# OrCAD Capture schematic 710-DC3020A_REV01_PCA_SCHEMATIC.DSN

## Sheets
1 LT8637: size Custom; company: ANALOG DEVICES; note: SILENT SWITCHER WITH 2.5uA QUIESCENT CURRENT; note: 42V, 5A(7A PEAK) SYNCHRONOUS STEP-DOWN
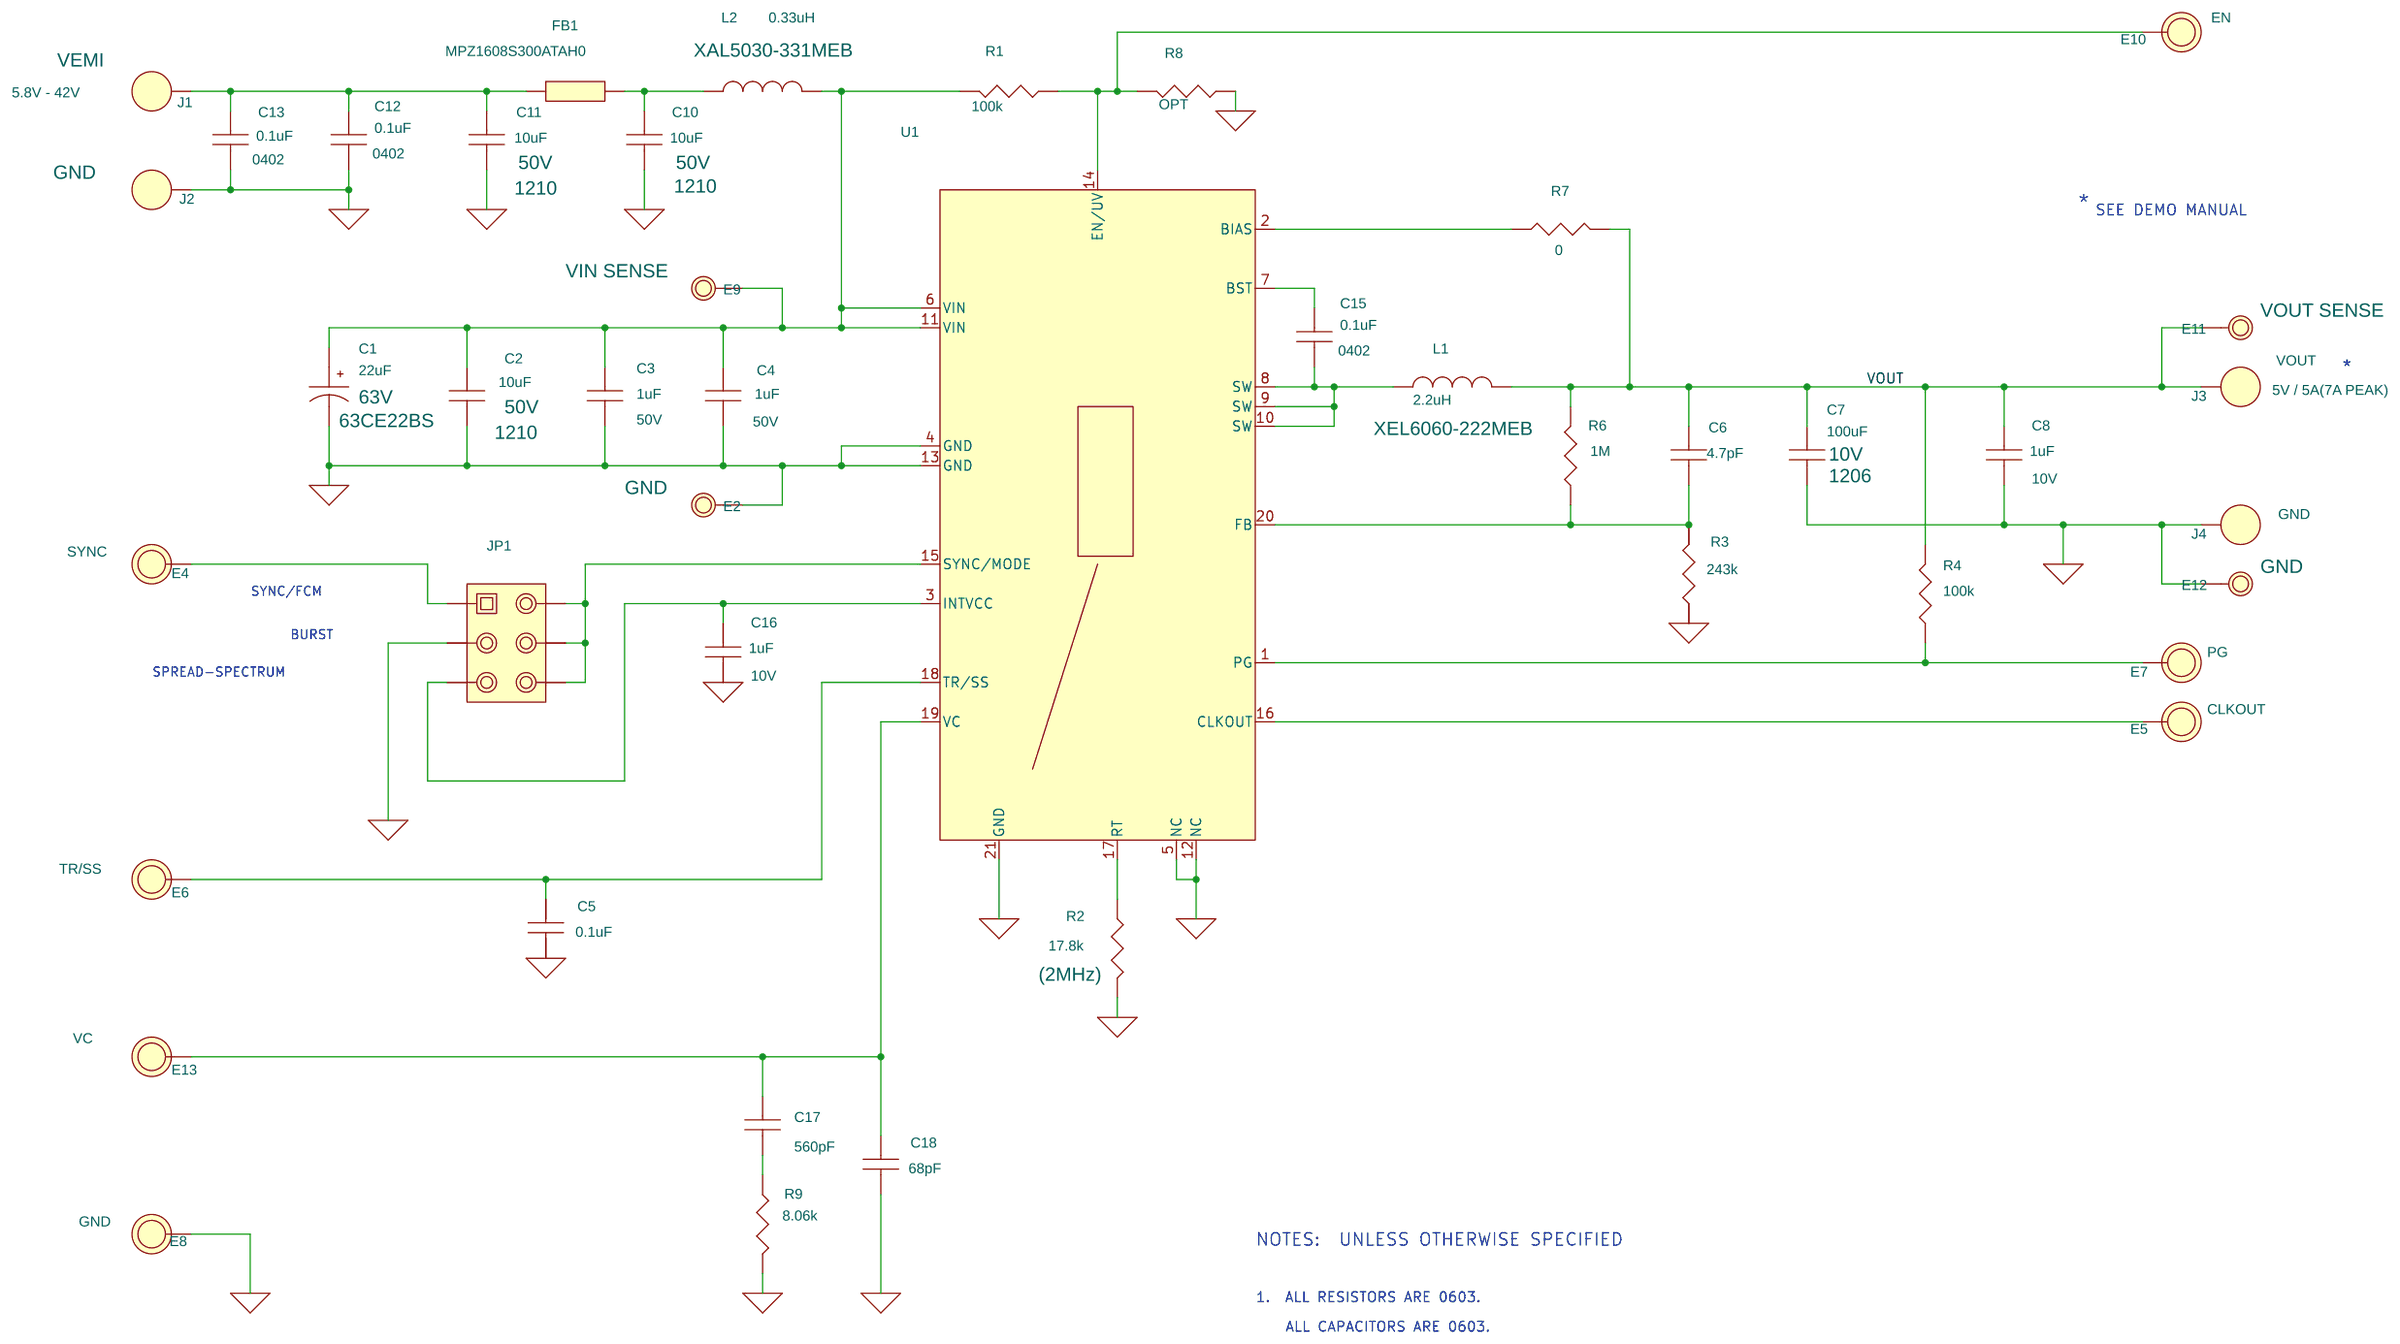
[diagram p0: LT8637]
2 PAGE2
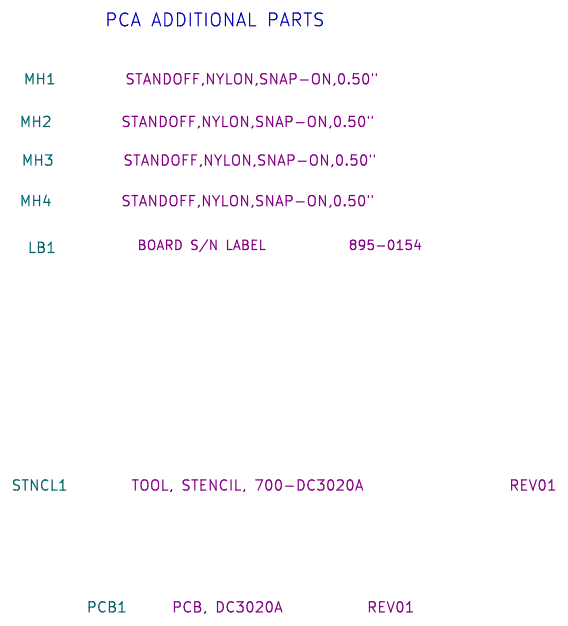
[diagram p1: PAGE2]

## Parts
sheet LT8637
C1  22uF  [SUNCON_CE-BS_6.3X7.7]
C2  10uF  [CC1210N]
C3  1uF  [CC0603N]
C4  1uF  [CC0603N]
C5  0.1uF  [CC0603N]
C6  4.7pF  [CC0603N]
C7  100uF  [CC1206N]
C8  1uF  [CC0603N]
C10  10uF  [CC1210N]
C11  10uF  [CC1210N]
C12  0.1uF  [CC0402N]
C13  0.1uF  [CC0402N]
C15  0.1uF  [CC0402N]
C16  1uF  [CC0603N]
C17  560pF  [CC0603N]
C18  68pF  [CC0603N]
E2  TEST POINT  [MILLMAX2308]
E4  TEST POINT  [MILLMAX2501]
E5  TEST POINT  [MILLMAX2501]
E6  TEST POINT  [MILLMAX2501]
E7  TEST POINT  [MILLMAX2501]
E8  TEST POINT  [MILLMAX2501]
E9  TEST POINT  [MILLMAX2308]
E10  TEST POINT  [MILLMAX2501]
E11  TEST POINT  [MILLMAX2308]
E12  TEST POINT  [MILLMAX2308]
E13  TEST POINT  [MILLMAX2501]
FB1  30 OHMS@100Mhz  [IND0603N]
J1  BANANA JACK  [KEY-575-4]
J2  BANANA JACK  [KEY-575-4]
J3  BANANA JACK  [KEY-575-4]
J4  BANANA JACK  [KEY-575-4]
JP1  HDR  [HD2X3-079]
L1  2.2uH  [COILCRAFT-XEL6060]
L2  0.33uH  [COILCRAFT-XAL50]
R1  100k  [CR0603N]
R2  17.8k  [CR0603N]
R3  243k  [CR0603N]
R4  100k  [CR0603N]
R6  1M  [CR0603N]
R7  0  [CR0603N]
R8  OPT  [CR0603N]
R9  8.06k  [CR0603N]
U1  LT8637-EV  [LTC-LQFN-20-1602]
XJP1  SHUNT  [SAMTEC-SHUNT-079]
sheet PAGE2
LB1  LABEL  [895-0154_REV01]
MH1  STANDOFF  [KEYSTONE_8829-8834]
MH2  STANDOFF  [KEYSTONE_8829-8834]
MH3  STANDOFF  [KEYSTONE_8829-8834]
MH4  STANDOFF  [KEYSTONE_8829-8834]
PCB1  PCB, DC3020A
STNCL1  TOOL, STENCIL, 700-DC3020A

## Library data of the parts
C1 = CAP_P_ALT: CAP.,22uF,ALUM ELECT,63V,20%,6.3x7.7mm,CE-BS Series; CLASS: DISCRETE; Dielectric Type: ALUM ELECT; Inventory Qty: 35661; Manufacturer: SUN ELECTRONIC INDUSTRIES CORP; Manufacturer PN: 63CE22BS; PART_NUMBER: 150-3334; Package Size: 6.3x7.7mm; Rated Voltage: 63V; Tolerance: 20%
C2 C10 C11 = CAP: CAP.,10uF,X7R,50V,10%,1210,NO SUBS. ALLOWED; CLASS: DISCRETE; Dielectric Type: X7R; FPLIST: CC1210N,CC1210L,CC1210M; Inventory Qty: 191942; Manufacturer: MURATA; Manufacturer PN: GRM32ER71H106KA12L; PART_NUMBER: 150-3043; Package Size: 1210; Package Type: SMD; Rated Voltage: 50V; Tolerance: 10%
C3 C4 = CAP: CAP.,1uF,X5R,50V,10%,0603; CLASS: DISCRETE; Dielectric Type: X5R; FPLIST: CC0603N,CC0603L,CC0603M; Inventory Qty: 11270; Manufacturer: AVX; Manufacturer PN: 06035D105KAT2A; PART_NUMBER: 150-3292; Package Size: 0603; Package Type: SMD; Rated Voltage: 50V; Tolerance: 10%
C5 = CAP: CAP.,0.1uF,X7R,16V,10%,0603; CLASS: DISCRETE; Dielectric Type: X7R; FPLIST: CC0603N,CC0603L,CC0603M; Inventory Qty: 38869; Manufacturer: MURATA; Manufacturer PN: GRM188R71C104KA01D; PART_NUMBER: 150-0018; Package Size: 0603; Package Type: SMD; Rated Voltage: 16V; Tolerance: 10%
C6 = CAP: CAP.,4.7pF,C0G/NP0,50V,+/-0.25pF,0603; CLASS: DISCRETE; Dielectric Type: C0G/NP0; FPLIST: CC0603N,CC0603L,CC0603M; Inventory Qty: 22709; Manufacturer: MURATA; Manufacturer PN: GRM1885C1H4R7CA01D; PART_NUMBER: 150-2223; Package Size: 0603; Rated Voltage: 50V; Tolerance: +/-0.25pF
C7 = CAP: CAP.,100uF,X5R,10V,20%,1206; CLASS: DISCRETE; Dielectric Type: X5R; FPLIST: CC1206N,CC1206L,CC1206M; Inventory Qty: 10889; Manufacturer: TDK; Manufacturer PN: C3216X5R1A107M160AC; PART_NUMBER: 150-2343; Package Size: 1206; Package Type: SMD; Rated Voltage: 10V; Tolerance: 20%
C8 C16 = CAP: CAP.,1uF,X7R,10V,10%,0603; CLASS: DISCRETE; Dielectric Type: X7R; FPLIST: CC0603N,CC0603L,CC0603M; Inventory Qty: 56548; Manufacturer: AVX; Manufacturer PN: 0603ZC105KAT2A; PART_NUMBER: 150-3414; Package Size: 0603; Rated Voltage: 10V; Tolerance: 10%
C12 C13 C15 = CAP: CAP.,0.1uF,X7R,50V,10%,0402; CLASS: DISCRETE; Dielectric Type: X7R; FPLIST: CC0402N,CC0402L,CC0402M; Inventory Qty: 321916; Manufacturer: AVX; Manufacturer PN: 04025C104KAT2A; PART_NUMBER: 150-3240; Package Size: 0402; Package Type: SMD; Rated Voltage: 50V; Tolerance: 10%
C17 = CAP: CAP.,560pF,C0G,50V,5%,0603; CLASS: DISCRETE; Dielectric Type: C0G; FPLIST: CC0603N,CC0603L,CC0603M; Inventory Qty: 0; Manufacturer: AVX; Manufacturer PN: 06035A561JAT2A; PART_NUMBER: 150-0112; Package Size: 0603; Rated Voltage: 50V; Tolerance: 5%
C18 = CAP: CAP.,68pF,C0G,50V,5%,0603; CLASS: DISCRETE; Dielectric Type: C0G; FPLIST: CC0603N,CC0603L,CC0603M; Inventory Qty: 14850; Manufacturer: AVX; Manufacturer PN: 06035A680JAT2A; PART_NUMBER: 150-0087; Package Size: 0603; Rated Voltage: 50V; Tolerance: 5%
E2 = TEST_POINT_.156_MILL-MAX_2308_A: TEST POINT,TURRET,0.064" MTG. HOLE,PCB 0.062" THK; 1ST PART FIELD: GND; CLASS: IO; Inventory Qty: 1142083; Manufacturer: MILL-MAX; Manufacturer PN: 2308-2-00-80-00-00-07-0; PART_NUMBER: 260-0004
E4 = TURRET_A: TEST POINT,TURRET,0.094" MTG. HOLE,PCB 0.062" THK; 9th Part Field: SYNC; CLASS: IO; FPLIST: MILLMAX2501,MILLMAX2501_ALT1; Inventory Qty: 823526; Manufacturer: MILL-MAX; Manufacturer PN: 2501-2-00-80-00-00-07-0; PART_NUMBER: 260-0003
E5 = TURRET_A: TEST POINT,TURRET,0.094" MTG. HOLE,PCB 0.062" THK; 9th Part Field: CLKOUT; CLASS: IO; FPLIST: MILLMAX2501,MILLMAX2501_ALT1; Inventory Qty: 823526; Manufacturer: MILL-MAX; Manufacturer PN: 2501-2-00-80-00-00-07-0; PART_NUMBER: 260-0003
E6 = TURRET_A: TEST POINT,TURRET,0.094" MTG. HOLE,PCB 0.062" THK; 9th Part Field: TR/SS; CLASS: IO; FPLIST: MILLMAX2501,MILLMAX2501_ALT1; Inventory Qty: 823526; Manufacturer: MILL-MAX; Manufacturer PN: 2501-2-00-80-00-00-07-0; PART_NUMBER: 260-0003
E7 = TURRET_A: TEST POINT,TURRET,0.094" MTG. HOLE,PCB 0.062" THK; 9th Part Field: PG; CLASS: IO; FPLIST: MILLMAX2501,MILLMAX2501_ALT1; Inventory Qty: 823526; Manufacturer: MILL-MAX; Manufacturer PN: 2501-2-00-80-00-00-07-0; PART_NUMBER: 260-0003
E8 = TURRET_A: TEST POINT,TURRET,0.094" MTG. HOLE,PCB 0.062" THK; 9th Part Field: GND; CLASS: IO; FPLIST: MILLMAX2501,MILLMAX2501_ALT1; Inventory Qty: 823526; Manufacturer: MILL-MAX; Manufacturer PN: 2501-2-00-80-00-00-07-0; PART_NUMBER: 260-0003
E9 = TEST_POINT_.156_MILL-MAX_2308_A: TEST POINT,TURRET,0.064" MTG. HOLE,PCB 0.062" THK; 1ST PART FIELD: VIN SENSE; CLASS: IO; Inventory Qty: 1142083; Manufacturer: MILL-MAX; Manufacturer PN: 2308-2-00-80-00-00-07-0; PART_NUMBER: 260-0004
E10 = TURRET_A: TEST POINT,TURRET,0.094" MTG. HOLE,PCB 0.062" THK; 10th Part Field: 5V / 6A; 9th Part Field: EN; CLASS: IO; FPLIST: MILLMAX2501,MILLMAX2501_ALT1; Inventory Qty: 823526; Manufacturer: MILL-MAX; Manufacturer PN: 2501-2-00-80-00-00-07-0; PART_NUMBER: 260-0003
E11 = TEST_POINT_.156_MILL-MAX_2308_A: TEST POINT,TURRET,0.064" MTG. HOLE,PCB 0.062" THK; 1ST PART FIELD: VEMI; 4TH PART FIELD: VOUT SENSE; CLASS: IO; Inventory Qty: 1142083; Manufacturer: MILL-MAX; Manufacturer PN: 2308-2-00-80-00-00-07-0; PART_NUMBER: 260-0004
E12 = TEST_POINT_.156_MILL-MAX_2308_A: TEST POINT,TURRET,0.064" MTG. HOLE,PCB 0.062" THK; 1ST PART FIELD: VEMI; 4TH PART FIELD: GND; CLASS: IO; Inventory Qty: 1142083; Manufacturer: MILL-MAX; Manufacturer PN: 2308-2-00-80-00-00-07-0; PART_NUMBER: 260-0004
E13 = TURRET_A: TEST POINT,TURRET,0.094" MTG. HOLE,PCB 0.062" THK; 9th Part Field: VC; CLASS: IO; FPLIST: MILLMAX2501,MILLMAX2501_ALT1; Inventory Qty: 823526; Manufacturer: MILL-MAX; Manufacturer PN: 2501-2-00-80-00-00-07-0; PART_NUMBER: 260-0003
FB1 = FERRITEBEAD_ALT1: IND.,30 OHMS@100MHz,FERRITE BEAD,25%,5A,10mOHMS,0603; CLASS: DISCRETE; FPLIST: IND0603N,IND0603L,IND0603M; Inventory Qty: 0; Manufacturer: TDK; Manufacturer PN: MPZ1608S300ATAH0; PART_NUMBER: 200-0753; Package Size: 0603; Tolerance: 25%
J1 = BANANA_KEYSTONE-575-4_C: CONN.,BANANA JACK,FEMALE,THT,NON-INSULATED,SWAGE,0.218"; 10th Part Field: 5.8V - 42V; 9th Part Field: VEMI; CLASS: IO; Inventory Qty: 203061; Manufacturer: KEYSTONE; Manufacturer PN: 575-4; PART_NUMBER: 250-0428
J2 = BANANA_KEYSTONE-575-4_C: CONN.,BANANA JACK,FEMALE,THT,NON-INSULATED,SWAGE,0.218"; 3RD PART FIELD: GND; CLASS: IO; Inventory Qty: 203061; Manufacturer: KEYSTONE; Manufacturer PN: 575-4; PART_NUMBER: 250-0428
J3 = BANANA_KEYSTONE-575-4_C: CONN.,BANANA JACK,FEMALE,THT,NON-INSULATED,SWAGE,0.218"; 10th Part Field: 5V / 5A(7A PEAK); 9th Part Field: VOUT; CLASS: IO; Inventory Qty: 203061; Manufacturer: KEYSTONE; Manufacturer PN: 575-4; PART_NUMBER: 250-0428
J4 = BANANA_KEYSTONE-575-4_C: CONN.,BANANA JACK,FEMALE,THT,NON-INSULATED,SWAGE,0.218"; 10th Part Field: 5V / 6A; 9th Part Field: GND; CLASS: IO; Inventory Qty: 203061; Manufacturer: KEYSTONE; Manufacturer PN: 575-4; PART_NUMBER: 250-0428
JP1 = HDR2X3_ALT1: CONN.,HDR,MALE,2x3,2mm,VERT,ST,THT; CLASS: IO; Inventory Qty: 17651; Manufacturer: WURTH ELEKTRONIK; Manufacturer PN: 62000621121; PART_NUMBER: 250-0483
L1 = IND_ALT: IND.,2.2uH,PWR,SHIELDED,20%,18.1A,6.70mOHMS,6.56x6.36mm,XEL6060,AEC-Q200; CLASS: DISCRETE; Inventory Qty: 0; Manufacturer: COILCRAFT; Manufacturer PN: XEL6060-222MEB; PART_NUMBER: 200-0802; Package Size: 6.56x6.36mm,XEL6060; Tolerance: 20%
L2 = IND_ALT: IND.,0.33uH,PWR,SHIELDED,20%,19.2A,3.52mOhms,5.48x5.28mm,XAL5030,AEC-Q200; CLASS: DISCRETE; Inventory Qty: 300; Manufacturer: COILCRAFT; Manufacturer PN: XAL5030-331MEB; PART_NUMBER: 200-0571; Package Size: 5.48x5.28mm,XAL5030; Tolerance: 20%
R1 R4 = RES: RES.,100k OHMS,1%,1/10W,0603,AEC-Q200; CLASS: DISCRETE; FPLIST: CR0603N,CR0603L,CR0603M; Inventory Qty: 185604; Manufacturer: VISHAY; Manufacturer PN: CRCW0603100KFKEA; PART_NUMBER: 100-0343; Package Size: 0603; Rated Power: 1/10W; Temperature Coefficient: +/-100ppm; Tolerance: 1%
R2 = RES: RES.,17.8k OHMS,1%,1/10W,0603,AEC-Q200; 4TH PART FIELD: (2MHz); CLASS: DISCRETE; FPLIST: CR0603N,CR0603L,CR0603M; Inventory Qty: 49144; Manufacturer: NIC; Manufacturer PN: NRC06F1782TRF; PART_NUMBER: 100-0867; Package Size: 0603; Rated Power: 1/10W; Temperature Coefficient: +/-100PPM; Tolerance: 1%
R3 = RES: RES.,243k OHMS,1%,1/10W,0603; CLASS: DISCRETE; FPLIST: CR0603N,CR0603L,CR0603M; Inventory Qty: 25701; Manufacturer: VISHAY; Manufacturer PN: CRCW0603243KFKEA; PART_NUMBER: 100-2672; Package Size: 0603; Rated Power: 1/10W; Temperature Coefficient: +/-100ppm/C; Tolerance: 1%
R6 = RES: RES.,1M OHM,1%,1/10W,0603,AEC-Q200; CLASS: DISCRETE; FPLIST: CR0603N,CR0603L,CR0603M; Inventory Qty: 165718; Manufacturer: VISHAY; Manufacturer PN: CRCW06031M00FKEA; PART_NUMBER: 100-0335; Package Size: 0603; Rated Power: 1/10W; Temperature Coefficient: 100ppm; Tolerance: 1%
R7 = RES: RES.,0 OHM,1/10W,0603,AEC-Q200; CLASS: DISCRETE; FPLIST: CR0603N,CR0603L,CR0603M; Inventory Qty: 701430; Manufacturer: VISHAY; Manufacturer PN: CRCW06030000Z0EA; PART_NUMBER: 100-0009; Package Size: 0603; Rated Power: 1/10W
R8 = RES: RES., OPTION, 0603; CLASS: DISCRETE; FPLIST: CR0603N,CR0603L,CR0603M; PART_NUMBER: 100-2374; Package Size: 0603
R9 = RES: RES.,8.06k OHMS,1%,1/10W,0603; CLASS: DISCRETE; FPLIST: CR0603N,CR0603L,CR0603M; Inventory Qty: 18284; Manufacturer: YAGEO; Manufacturer PN: RC0603FR-078K06L; PART_NUMBER: 100-0161; Package Size: 0603; Rated Power: 1/10W; Temperature Coefficient: 100ppm/C; Tolerance: 1%
U1 = LT8637-LQFN: IC,Syn. Step-Down Silent Switcher,LQFN-20,42V,6A; CLASS: IC; Inventory Qty: 0; Manufacturer: ANALOG DEVICES; Manufacturer PN: LT8637EV#PBF; PART_NUMBER: LT8637EV#PBF; Package Type: LQFN-20
XJP1 = SHUNT_2MM_C: CONN.,SHUNT,FEMALE,2-POS,2mm; CLASS: MECHANICAL; Inventory Qty: 268933; Manufacturer: SAMTEC; Manufacturer PN: 2SN-BK-G; PART_NUMBER: 250-0419
LB1 = BLANK_LABEL: LABEL SPEC, DEMO BOARD SERIAL NUMBER; Inventory Qty: 0; Manufacturer: BRADY; Manufacturer PN: THT-96-717-10; PART_FIELD_01: BOARD S/N LABEL; PART_NUMBER: 895-0154
MH1-MH4 = BLANK_MECHANICAL_PART: STANDOFF,NYLON,SNAP-ON,0.50"; CLASS: DISCRETE; FPLIST: KEYSTONE_8829-8834,MTG-8831; Inventory Qty: 9249; Manufacturer: WURTH ELEKTRONIK; Manufacturer PN: 702935000; PART_NUMBER: 763-0020
PCB1 = BLANK_PCB_PART: BOM Notes: REV01; CLASS: DISCRETE; Inventory Qty: 0; Manufacturer: ADI APPROVED SUPPLIER; Manufacturer PN: 600-DC3020A; PART_NUMBER: 600-DC3020A
STNCL1 = BLANK_STENCIL_PART: BOM Notes: REV01; CLASS: DISCRETE; Inventory Qty: 0; Manufacturer: ADI APPROVED SUPPLIER; Manufacturer PN: 830-DC3020A; PART_NUMBER: 830-DC3020A

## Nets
GND_SIGNAL: C1.2 C2.2 C3.2 C4.2 C5.2 C7.2 C8.2 C10.2 C11.2 C12.2 C13.2 C16.2 C18.2 E2.1 E8.1 E12.1 J2.1 J4.1 JP1.3 R2.1 R3.1 R8.1 R9.2 U1.4(GND) U1.5(NC) U1.12(NC) U1.13(GND) U1.21(GND)
VOUT: C6.1 C7.1 C8.1 E11.1 J3.1 L1.2 R4.1 R6.2 R7.2
N16844188: C1.1 C2.1 C3.1 C4.1 E9.1 L2.2 R1.2 U1.6(VIN) U1.11(VIN)
N16983256: E7.1 R4.2 U1.1(PG)
N16987190: E4.1 JP1.1
N16989137: JP1.2 JP1.4 JP1.6 U1.15(SYNC/MODE)
N17010759: R2.2 U1.17(RT)
N17036639: C16.1 JP1.5 U1.3(INTVCC)
N17044712: C5.1 E6.1 U1.18(TR/SS)
N17168400: C11.1 C12.1 C13.1 FB1.1 J1.1
N17200447: C15.2 L1.1 U1.8(SW) U1.9(SW) U1.10(SW)
N17201126: C6.2 R3.2 R6.1 U1.20(FB)
N17201723: E5.1 U1.16(CLKOUT)
N17204042: R7.1 U1.2(BIAS)
N17210499: E10.1 R1.1 R8.2 U1.14(EN/UV)
N17214032: C10.1 FB1.2 L2.1
N17256278: C15.1 U1.7(BST)
N17298301: C17.1 C18.1 E13.1 U1.19(VC)
N17298347: C17.2 R9.1

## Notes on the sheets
sheet 1
- *
- SEE DEMO MANUAL
- *
- SYNC/FCM
- BURST
- SPREAD-SPECTRUM
- NOTES:  UNLESS OTHERWISE SPECIFIED
- 1.  ALL RESISTORS ARE 0603.
- ALL CAPACITORS ARE 0603.
sheet 2
- PCA ADDITIONAL PARTS
